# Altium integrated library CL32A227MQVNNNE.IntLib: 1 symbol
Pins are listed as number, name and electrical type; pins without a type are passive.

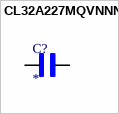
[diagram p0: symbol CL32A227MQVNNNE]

## CL32A227MQVNNNE
designator C?
CL32 Series 1210 220 uF 6.3 V Â±20% Tolerance X5R Multilayer Ceramic Capacitor; MF: Samsung Electro-Mechanics; MP: CL32A227MQVNNNE
footprint ANTC3225X280N
pins: 1, 2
